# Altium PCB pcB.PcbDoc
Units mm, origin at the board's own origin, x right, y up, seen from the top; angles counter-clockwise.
Board outline 112 x 24 mm, 2 copper layers (TopLayer, BottomLayer); 32 components, 27 nets, 88 pads, 0 vias.
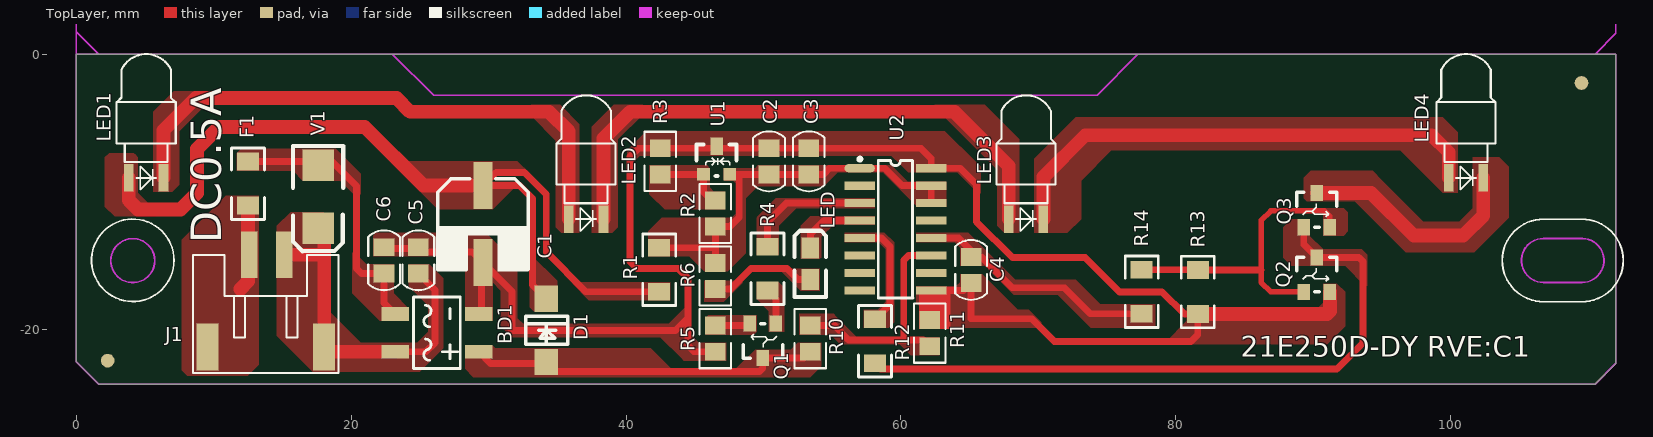
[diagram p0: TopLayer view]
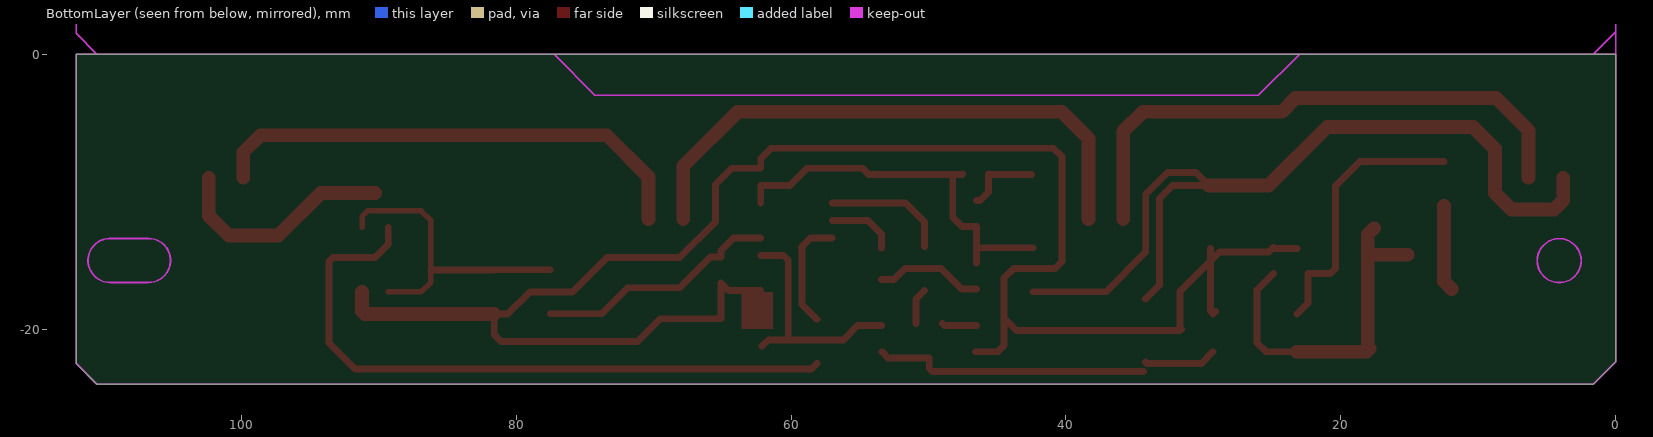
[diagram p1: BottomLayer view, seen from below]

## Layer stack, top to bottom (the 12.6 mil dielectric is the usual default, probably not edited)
TopLayer: signal copper 0.0356
Dielectric: core 0.32, FR-4, Dk 4.8
BottomLayer: signal copper 0.0356

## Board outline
112.003,-22.5 110.5,-24.003 1.641,-24.003 0,-22.362 0,0 112,0

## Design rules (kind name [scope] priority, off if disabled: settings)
Clearance Clearance_1 [InNet(GND)] p1: gap=0.5
Clearance [All] p2 off: gap=0.3
PlaneConnect [All] p1: planeconnectstyle=Direct reliefexpansion=0.508 reliefentries=4 reliefconductorwidth=0.254 reliefairgap=0.254
PolygonConnect [All] p1: connectstyle=Direct reliefconductorwidth=0.254 reliefentries=4 polygonreliefangle="90 Angle"
RoutingVias [All] p1: holewidth=0.5 width=0.8 viastyle="Through Hole" minholewidth=0.3 minwidth=0.6 maxholewidth=1 maxwidth=1.5
SilkscreenOverComponentPads [All] p1: minsilkscreentomaskgap=0.254
SolderMaskExpansion [All] p1: expansion=0.102
TestPointUsage [All] p1: valid=0 allowmultiple=FALSE
Testpoint [All] p1: side=3 testpointundercomponent=TRUE minsize=1.016 maxsize=2.54 preferedsize=1.524 minholesize=0.508 maxholesize=1.016 preferedholesize=0.813 testpointgrid=0.025 style=297 order=0-112345678
Width [All] p1: maxlimit=5 minlimit=0.254 preferedwidth=0.254 toplayer_prefwidth=0.5 bottomlayer_prefwidth=0.5 minimp=50.000000 maximp=50.000000 favimp=50.000000
22 further rules are at their usual default settings.

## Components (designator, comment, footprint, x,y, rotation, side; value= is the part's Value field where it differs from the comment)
BD1 "MB10S" BM6S 23.2,-18.9 r0 top
C1 "22uf/50V" CES6.3 26,-7.7 r0 top
C2 "0805 105/50V 0.1uf  X7R" 0805-C 50.4,-7.8 r270 top
C3 "0805 104/50V 0.1uf  X7R" 0805-C 53.3,-7.8 r270 top
C4 "0805 104/50V 0.1uf  X7R" 0805-C 65.1,-15.7 r90 top
C5 "0805 30PF/50V  X7R" 0805-C 24.9,-15 r270 top
C6 "0805 30PF/50V  X7R" 0805-c 22.4,-15 r90 top
D1 "ES1J" sma 34.2,-20.1 r180 top
F1 "(贴片0.5A)" 1206 12.521,-9.414 r90 top
J1 "卧插座子2.54mm 2P" XH-2.5-2PTW 12.6,-14.6 r0 top
LED "" LED0805 53.4,-16.4 r90 top
LED1 "" LED2_l 5.1,-9 r0 top locked
LED2 "" LED2_l 37.1,-12 r0 top locked
LED3 "" LED2_l 69.1,-12 r0 top locked
LED4 "" LED2_l 101.1,-9 r0 top locked
Q1 "BC846ALT1" SOT-23 50.9,-19.6 r180 top
Q2 "s8050" SOT-23 89.3,-17.3 r0 top
Q3 "s8050" SOT-23 89.3,-12.6 r0 top
R1 "1206 4.7K±5%" 1206 42.4,-15.7 r270 top
R2 "0805 10K±5%" 0805 46.5,-11.6 r270 top
R3 "0805 10K±5%" 0805 42.5,-7.8 r270 top
R4 "1206 1KΩ±5%" 1206 50.3,-15.6 r90 top
R5 "0805 100Ω±5%" 0805 46.5,-20.7 r90 top
R6 "0805 20K±5%" 0805 46.5,-16.15 r90 top
R10 "0805 200K±5%" 0805 53.4,-20.7 r270 top
R11 "0805 30K±5%" 0805 62.1,-20.3 r270 top
R12 "1206 4.7K±5%" 1206 58.1,-20.9 r270 top
R13 "1206 51Ω±5%" 1206 81.6,-17.3 r90 top
R14 "1206 10K±5%" 1206 77.5,-17.3 r270 top
U1 "TL431" SOT23-A2 46.6,-6.7 r0 top
U2 "SOP16" SOP-16b 57,-8.3 r0 top
V1 "P6KE36CA" SMT_TVS 17.6,-8.1 r270 top

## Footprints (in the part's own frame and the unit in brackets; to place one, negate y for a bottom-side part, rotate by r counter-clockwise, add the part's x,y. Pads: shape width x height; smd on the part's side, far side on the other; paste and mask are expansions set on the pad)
0805 [mm]
  rect 1.3x1.5 smd: 1(-0.95,0) 2(0.95,0)
  silkscreen extent -2.15,-1.15 2.15,1.15
0805-C [mm]
  rect 1.3x1.5 smd: 1(-0.95,0) 2(0.95,0)
  silkscreen extent -2.18,-1.15 2.18,1.15
0805-c [mm]
  rect 1.3x1.5 smd: 1(-0.95,0) 2(0.95,0)
  silkscreen extent -2.18,-1.15 2.18,1.15
1206 [mm]
  rect 1.3x1.6 smd: 1(-1.61,0.009) 2(1.59,0.009)
  silkscreen extent -2.61,-1.19 2.59,1.21
BM6S [mm]
  rect 2x1 smd: 1(0,0) 2(0,-2.75) 3(6.096,-2.75) 4(6.096,0)
  silkscreen extent 1.35,-3.97 4.75,1.23
CES6.3 [mm]
  rect 1.4x3.4 smd: 1(3.596,-1.864) 2(3.596,-7.464)
  silkscreen extent 0.3,-8.1 6.9,-1.36
LED2_l [mm]
  rect 0.7x2 smd: A(-1.26,0) K(1.26,0)
  silkscreen extent -2.15,-0.87 2.15,9
LED0805 [mil]
  rect 60x50 smd: A(0,-0.31) K(90,-0.31)
  silkscreen extent -50,-45 140,45
sma [mm]
  rect 1.7x1.905 smd: A(-0.003,2.302) K(-0.003,-2.298)
  silkscreen extent -1.58,-1.01 1.5,1.02
SMT_TVS [mil]
  rect 90x90 smd: A(0,0) K(180,0)
  silkscreen extent -56,-72 246,72
SOP-16b [mm]
  oval 2.2x0.6 smd: 1(0,0)
  rect 2.2x0.6 smd: 2(0,-1.27) 3(0,-2.54) 4(0,-3.81) 5(0,-5.08) 6(0,-6.35) 7(0,-7.62) 8(0,-8.89) 9(5.2,-8.89) 10(5.2,-7.62) 11(5.2,-6.35) 12(5.2,-5.08) 13(5.2,-3.81) 14(5.2,-2.54) 15(5.2,-1.27) 16(5.2,0)
  silkscreen extent -0.11,-9.44 3.87,0.79
SOT23-A2 [mil]
  rect 36x36 smd: 1(-38,-80) 2(37,-80)
  rect 36x50 smd: 3(0,0)
  silkscreen extent -58,-85 57,5
SOT-23 [mm]
  rect 0.918x1.18 smd: 1(0,0) 2(1.9,0) 3(0.95,2.5)
  silkscreen extent -0.51,0 2.39,2.54
XH-2.5-2PTW [mm]
  rect 1.6x3.4 smd: 0(-3.05,-6.7) 0(5.45,-6.7)
  rect 1.2x3.4 smd: 1(0,0) 2(2.54,0)
  silkscreen extent -4.1,-8.6 6.5,0

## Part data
BD1: library part BRIDGE2
C1 C2 C3 C4 C5 C6: library part CAP
D1: library part Diode, "Common Diode"
F1: library part FUSE1
J1: library part CON2
LED LED1 LED2 LED3 LED4: library part LED
Q1 Q2 Q3: library part NPN
R1 R2 R3 R5 R12 R14: library part RES1
R4 R10 R11 R13: library part RES2
R6: library part RES
U1: library part HT66F004_SOP16
U2: library part HT7463B
V1: library part TVS1

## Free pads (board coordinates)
  round 1 smd: 0(2.3,-22.3) 0(109.5,-2.1)

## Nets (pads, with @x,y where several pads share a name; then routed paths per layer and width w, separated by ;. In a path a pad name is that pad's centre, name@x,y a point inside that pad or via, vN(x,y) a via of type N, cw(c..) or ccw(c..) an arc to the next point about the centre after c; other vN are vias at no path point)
5.0V: C2.2 C3.2 R1.1 R2.2 R6.2 U1.2 U2.1 U2.14 U2.15 | length 28.6
  TopLayer w0.5: R1.1 46.41,-14.09 46.5,-14 ; R6.2 46.5,-14 ; U1.2 47.558,-8.75 48.24,-8.75 ; C3.2@53.988,-8.732 C3.2@54,-8.72 ; U2.14 U2.15 60.07,-9.57 58.8,-8.3 U2.1 54.8,-8.3 54.35,-8.75 C3.2 C2.2 48.24,-8.75 ; 46.5,-14 R2.2 47.55,-12.55 48.24,-11.86 48.24,-8.75
ADBT: U2.10
ALD1: C4.2 R14.2 U2.12 | length 17.9
  TopLayer w0.5: U2.12 64.2,-13.38 65.1,-14.28 C4.2 65.85,-14.75 68.1,-17 71.9,-17 73.79,-18.89 R14.2
CHARGE: U2.2
EN1: R12.1 U2.5 | length 8.2
  TopLayer w0.5: U2.5 58.58,-13.38 59.2,-14 59.2,-18.2 R12.1
EN2: U2.6
EN3: U2.13
GND: BD1.4 C1.2 C2.1 C3.1 C4.1 C5.1 C6.2 Q2.2 R3.1 R5.1 R11.1 R13.1 U1.3 U2.9 U2.16 | length 135.3
  TopLayer w0.5: 23.2,-14.15 C5.1@24.9,-14.15 ; C5.1 25.25,-14.4 28.832,-14.4 C1.2@29.496,-15.064 ; BD1.4@29.111,-18.715 BD1.4 29.496,-18.7 C1.2@29.496,-15.064 ; C1.2@29.496,-14.15 C1.2@29.496,-15.064 ; 31.6,-20 31.7,-20.1 ; 31.9,-20.1 32.4,-20.1 ; R5.1@46.6,-21.65 R5.1 44.95,-21.65 44.5,-21.2 44.5,-19.2 ; U2.9 64.56,-17.19 C4.1 65.1,-19.25 69.5,-19.25 71.15,-20.9 81.1,-20.9 81.591,-20.409 R13.1 80.61,-18.91 79,-17.3 75.9,-17.3 73.4,-14.8 68.1,-14.8 65.5,-12.2 65.5,-9.5 64.3,-8.3 U2.16 62.2,-7.6 61.45,-6.85 R3.1 40.9,-6.85 40.3,-7.45 40.3,-15.1 40.8,-15.6 43.8,-15.6 44.5,-16.3 44.5,-19.2 ; C1.2@29.496,-15.064 C1.2 31.7,-17.268 31.7,-20.1 ; 31.7,-20.1 32.4,-20.1 ; 32.4,-20.1 43.6,-20.1 44.5,-19.2
  TopLayer w1: R13.1 90.99,-18.91 91.2,-18.7 Q2.2
LED: LED.K U2.4 | length 5
  TopLayer w0.5: LED.K 53.408,-13.092 54.39,-12.11 U2.4
NetBD1_1: BD1.1 C6.1 F1.2 V1.A | length 20.1
  TopLayer w0.5: F1.2 18.624,-7.824 20.4,-9.6 20.4,-15.6 20.75,-15.95 C6.1 22.4,-18.1 BD1.1
NetBD1_2: BD1.2 C5.2 J1.0@18.05,-21.3 J1.2 V1.K | length 25.8
  TopLayer w0.5: BD1.2 25.45,-21.65 26.1,-21 26.1,-17.15 C5.2
  TopLayer w1: J1.2 18.05,-14.6 ; V1.K 18.05,-13.122 18.05,-14.6 ; J1.0@17.925,-21.425 18.15,-21.65 BD1.2 ; J1.0@18.05,-21.3 18.05,-14.6
NetF1_1: F1.1 J1.1 | length 6.3
  TopLayer w1: 11.951,-17.084 12.512,-16.523 F1.1
NetLED1_K: LED1.K LED2.A | length 41.3
  TopLayer w1: LED1.K 6.36,-5.54 8.7,-3.2 23.3,-3.2 24.3,-4.2 34.4,-4.2 35.84,-5.64 LED2.A
NetLED2_K: LED2.K LED3.A | length 41.6
  TopLayer w1: LED2.K 38.36,-6.14 40.3,-4.2 63.9,-4.2 67.84,-8.14 LED3.A
NetLED3_K: LED3.K LED4.A | length 36.2
  TopLayer w1: LED3.K 70.36,-8.94 73.4,-5.9 98.6,-5.9 99.84,-7.14 LED4.A
NetLED4_K: LED4.K Q3.3 | length 16.7
  TopLayer w1: Q3.3 94.2,-10.1 97.3,-13.2 100.9,-13.2 102.36,-11.74 LED4.K
NetLED_A: LED.A R6.1 | length 7.9
  TopLayer w0.5: R6.1 47.6,-17.1 49.1,-15.6 51.7,-15.6 52.5,-16.4 LED.A
NetQ1_1: Q1.1 R4.1 | length 2.6
  TopLayer w0.5: R4.1 50.9,-17.819 Q1.1
NetQ1_2: Q1.2 R5.2 | length 2.6
  TopLayer w0.5: R5.2 48.85,-19.75 Q1.2
NetQ2_1: Q2.1 Q3.2 R13.2 R14.1 | length 23.2
  TopLayer w0.4: Q2.1 86.9,-17.3 86.2,-16.6 86.2,-15.7 86.2,-12.1 86.9,-11.4 90.8,-11.4 91.2,-11.8 Q3.2 Q3.2@91.2,-12.2
  TopLayer w0.5: R14.1 R13.2@81.571,-15.69 ; R13.2 86.19,-15.71 86.2,-15.7
NetQ2_3: Q2.3 Q3.1 R12.2 | length 48.4
  TopLayer w0.5: R12.2 58.519,-22.9 91.7,-22.9 93.6,-21 93.6,-15.1 93.3,-14.8 Q2.3 89.3,-13.85 Q3.1
NetR2_1: R2.1 R3.2 U1.1 | length 5.6
  TopLayer w0.5: R3.2 U1.1@45.635,-8.75 ; R2.1 46.25,-10.65 45.635,-10.035 U1.1@45.635,-8.75 ; U1.1@45.635,-8.75 45.653,-8.75 U1.1 U1.1@45.635,-8.75
PI: R10.1 R11.2 U2.11 | length 17.2
  TopLayer w0.5: R10.1 55.15,-19.75 56.2,-20.8 60.1,-20.8 ; R11.2 61.65,-20.8 60.2,-20.8 60.2,-15 60.55,-14.65 U2.11
PO: R4.2 U2.3 | length 9.1
  TopLayer w0.5: R4.2 50.291,-12.209 51.66,-10.84 U2.3
SENSOR: U2.8
V+: BD1.3 D1.A Q1.3 R10.2 | length 25.4
  TopLayer w0.5: BD1.3 30.146,-22.5 34.105,-22.5 D1.A ; D1.A@34.368,-23.1 49.7,-23.1 49.95,-22.85 Q1.3 52.95,-22.1 R10.2
VV+: C1.1 D1.K LED1.A R1.2 | length 64.8
  TopLayer w0.5: D1.K 33.2,-16.798 33.2,-10.5 32.264,-9.564 C1.1 30.56,-8.6 32.6,-8.6 34.2,-10.2 34.2,-14.4 37.09,-17.29 R1.2
  TopLayer w1: LED1.A 3.84,-10.64 4.5,-11.3 7.6,-11.3 8.8,-10.1 8.8,-6.9 10.4,-5.3 21,-5.3 25.264,-9.564 C1.1
pads on no net: J1.0@9.55,-21.3 U2.7

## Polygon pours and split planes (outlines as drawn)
5.0V on TopLayer "Bottom Layer-No Net" (solid, remove dead copper, pour order 1000): 41.6,-14.7 44.6,-14.7 45.7,-15.8 47.4,-15.8 48.5,-14.7 48.7,-14.5 48.7,-8.8 48,-8.8 48,-11.6 47.7,-11.9 42.6,-11.9 41.6,-12.9
5.0V on TopLayer "Bottom Layer-No Net" (solid, remove dead copper, pour order 1001): 47.1,-8.3 49.4,-8.3 49.6,-8.1 59.3,-8.1 60.1,-8.9 60.5,-9.3 63.3,-9.3 63.3,-11.1 61.2,-11.1 58.8,-8.7 58.7,-8.6 56.5,-8.6 55.4,-8.6 54.4,-9.6 49.6,-9.6 48.6,-10.6 48.1,-10.6 48.1,-9.5 47.8,-9.2 47.1,-9.2
ALD1 on TopLayer "Bottom Layer-No Net" (solid, remove dead copper, pour order 1002): 61.1,-13.7 63.9,-13.7 64.3,-14.1 64.3,-15.4 66.1,-15.4 67.5,-16.8 68.2,-17.5 71.4,-17.5 73.8,-19.9 78.5,-19.9 78.5,-18.2 74.5,-18.2 73,-16.7 72.7,-16.4 69.5,-16.4 68.3,-16.4 65.3,-13.4 64.9,-13 61.1,-13
EN1 on TopLayer "Bottom Layer-No Net" (solid, remove dead copper, pour order 1003): 57.3,-19.9 59.1,-19.9 59.4,-19.6 59.5,-19.5 59.5,-15.7 59.5,-13.7 58.8,-13 55.9,-13 55.9,-13.7 58.4,-13.7 58.9,-14.2 58.9,-18 58.3,-18.6 57.3,-18.6
GND on TopLayer "Bottom Layer-No Net" (solid, remove dead copper, pour order 1004): 61.1,-16.9 64,-16.9 64.3,-16.6 64.3,-16 65.9,-16 68.5,-18.6 69.1,-18.6 69.3,-18.6 70.2,-19.5 70.2,-19.8 70.1,-19.9 63.1,-19.9 62.9,-19.9 61.1,-18.1
GND on TopLayer "Bottom Layer-No Net" (solid, remove dead copper, pour order 1005): 90.7,-16.7 90.7,-18.1 90.4,-18.4 80.8,-18.4 80.8,-19.4 79.1,-21.1 91,-21.1 92.2,-19.9 92.3,-19.8 92.3,-17.3 91.7,-16.7
GND on TopLayer "Bottom Layer-No Net" (solid, remove dead copper, pour order 1006): 61.1,-8.6 64.1,-8.6 65.4,-9.9 65.8,-10.3 65.8,-8.2 65.4,-7.8 63.2,-5.6 41.3,-5.6 41.3,-5.8 40.1,-7 40.1,-7.8 40.6,-7.8 40.9,-7.5 41,-7.4 46.8,-7.4 59.3,-7.4 60.5,-8.6
GND on TopLayer "Bottom Layer-No Net" (solid, remove dead copper, pour order 1007): 47.3,-21 45.3,-21 44.7,-20.4 44.7,-18 43.1,-19.6 32.1,-19.6 30.9,-19.6 31.9,-20.6 32.9,-20.6 42.5,-20.6 44,-22.1 44.2,-22.3 47.3,-22.3
LED on TopLayer "Bottom Layer-No Net" (solid, remove dead copper, pour order 1010): 52.7,-14.9 52.7,-12.5 53.4,-11.8 58.1,-11.8 58.1,-12.4 55.1,-12.4 54.2,-13.3 54.2,-14.8 54.1,-14.9
NetF1_1 on TopLayer "Bottom Layer-No Net" (solid, remove dead copper, pour order 1013): 13.3,-10.3 13.3,-22.6 12.5,-23.4 8.1,-23.4 7.7,-23 7.7,-13.5 10.9,-10.3
NetLED1_K on TopLayer "Bottom Layer-No Net" (solid, remove dead copper, pour order 1014): 5.6,-10 5.6,-4.2 7.1,-2.7 9.8,-2.7 9.8,-3.3 9.1,-4 7.5,-5.6 7.5,-9.5 7,-10
NetLED2_K on TopLayer "Bottom Layer-No Net" (solid, remove dead copper, pour order 1015): 37.5,-13 37.5,-5.3 39.1,-3.7 41.2,-3.7 41.2,-4.4 39.4,-6.2 39.4,-12.6 39,-13
NetLED1_K on TopLayer "Bottom Layer-No Net" (solid, remove dead copper, pour order 1016): 36.6,-13 36.6,-5.1 35.2,-3.7 33.1,-3.7 33.1,-4.5 34.9,-6.3 34.9,-7 34.9,-12.6 35.3,-13
NetLED2_K on TopLayer "Bottom Layer-No Net" (solid, remove dead copper, pour order 1017): 68.6,-13 68.6,-6.2 66.9,-4.5 66.1,-3.7 62.3,-3.7 67,-8.4 67,-9.2 67,-12.5 67.5,-13
NetLED3_K on TopLayer "Bottom Layer-No Net" (solid, remove dead copper, pour order 1018): 69.7,-13 69.7,-7.6 72.5,-4.8 72.7,-4.6 81.4,-4.6 99.4,-4.6 100.5,-5.7 100.5,-10.1 99.4,-10.1 97.8,-8.5 96.3,-7 95.4,-7 75.3,-7 73.1,-9.2 73.1,-12 72.1,-13
NetLED4_K on TopLayer "Bottom Layer-No Net" (solid, remove dead copper, pour order 1019): 101.6,-7.5 101.6,-11.2 100.7,-12.1 100.6,-12.2 98.3,-12.2 98,-12.2 95,-9.2 94.3,-8.5 89.8,-8.5 89.3,-9 89.3,-9.1 89.3,-10.5 89.5,-10.7 93,-10.7 95.4,-13.1 96.7,-14.4 101.5,-14.4 101.7,-14.4 104.2,-11.9 104.2,-8.2 103.5,-7.5
NetLED_A on TopLayer "Bottom Layer-No Net" (solid, remove dead copper, pour order 1020): 54.1,-15.6 51.4,-15.6 51.3,-15.6 51.3,-15.8 52.7,-17.2 54.1,-17.2
NetLED_A on TopLayer "Bottom Layer-No Net" (solid, remove dead copper, pour order 1021): 45.7,-16.5 48.6,-16.5 47.1,-18 45.7,-18
NetQ1_1 on TopLayer "Bottom Layer-No Net" (solid, remove dead copper, pour order 1022): 50.4,-20.2 50.4,-18.7 49.5,-17.8 49.5,-16.6 51.1,-16.6 51.5,-17 51.5,-20.2
NetQ1_2 on TopLayer "Bottom Layer-No Net" (solid, remove dead copper, pour order 1023): 45.8,-20.4 49.3,-20.4 49.5,-20.2 49.5,-19 46,-19 45.8,-19.2
NetQ2_1 on TopLayer "Bottom Layer-No Net" (solid, remove dead copper, pour order 1024): 90.7,-13.2 90.7,-11.7 90.2,-11.2 92.2,-11.2 92.5,-11.5 92.5,-12.9 92.2,-13.2
NetQ2_3 on TopLayer "Bottom Layer-No Net" (solid, remove dead copper, pour order 1025): 89.7,-12 89.7,-13.2 90.7,-14.2 93.5,-14.2 93.9,-14.6 93.9,-17 92.3,-15.4 91,-15.4 88.4,-15.4 87.8,-14.8 87.8,-12.6 88.4,-12
NetR2_1 on TopLayer "Bottom Layer-No Net" (solid, remove dead copper, pour order 1026): 47.2,-11.3 42.8,-11.3 41.8,-10.3 41.7,-10.2 41.7,-8.1 45.9,-8.1 46.1,-8.3 46.1,-9.7 46.4,-10 47.2,-10
PI on TopLayer "Bottom Layer-No Net" (solid, remove dead copper, pour order 1027): 62.8,-20.6 56.8,-20.6 55.3,-19.1 55.1,-18.9 52.6,-18.9 52.6,-20.4 54.9,-20.4 55.6,-21.1 59.9,-21.1 60.7,-21.9 62.8,-21.9
PO on TopLayer "Bottom Layer-No Net" (solid, remove dead copper, pour order 1028): 58.1,-10.5 50.9,-10.5 49.6,-11.8 49.5,-11.9 49.5,-14.6 51.1,-14.6 51.1,-12.5 52.4,-11.2 58.1,-11.2
V+ on TopLayer "Bottom Layer-No Net" (solid, remove dead copper, pour order 1029): 54.2,-21 52.5,-21 52,-21.5 49.4,-21.5 48,-22.9 43.3,-22.9 41.9,-21.5 41.8,-21.4 30.5,-21.4 30.3,-21.2 28.3,-21.2 28.3,-22.9 28.9,-23.5 53.4,-23.5 54.2,-22.7
VV+ on TopLayer "Bottom Layer-No Net" (solid, remove dead copper, pour order 1032): 5.8,-11.8 2.8,-11.8 2.1,-11.1 2.1,-7.5 2.4,-7.2 4.2,-7.2 4.3,-7.3 4.5,-7.5 4.5,-9.4 4.5,-10.1 5.8,-11.4
GND on TopLayer "Bottom Layer-No Net" (solid, remove dead copper, pour order 1000): 32.4,-20.6 31.7,-20.6 30.9,-19.8 30.9,-17.2 30.3,-16.6 30.3,-19.4 28.3,-19.4 28.3,-15.8 27.5,-15 27.2,-14.7 24.1,-14.7 21.6,-14.7 21.6,-13.2 21.8,-13 29.8,-13 30.3,-13.5 32.1,-15.3 32.1,-18.1 32.1,-19.2 32.6,-19.7 32.6,-20.6
VV+ on TopLayer "Bottom Layer-No Net" (solid, remove dead copper, pour order 1001): 43.2,-16.6 36,-16.6 37.3,-17.9 43.2,-17.9
VV+ on TopLayer "Bottom Layer-No Net" (solid, remove dead copper, pour order 1002): 35,-18.7 35,-16.5 33,-14.5 33,-18.4 33.3,-18.7
VV+ on TopLayer "Bottom Layer-No Net" (solid, remove dead copper, pour order 1003): 30.3,-7.8 22.8,-7.8 26.3,-11.3 30.3,-11.3 31.9,-9.7 31.9,-9.3 29.8,-9.3 29.6,-9.5 30.3,-8.8 32.7,-8.8 33.1,-8.8 32.1,-7.8 31.7,-7.8
NetBD1_1 on TopLayer "Bottom Layer-No Net" (solid, remove dead copper, pour order 1004): 24.1,-19.4 24.1,-18.4 23.2,-17.5 23.1,-17.4 23.1,-15.3 21.1,-15.3 20.1,-14.3 20.1,-17.4 22.1,-19.4
NetBD1_2 on TopLayer "Bottom Layer-No Net" (solid, remove dead copper, pour order 1005): 24.2,-15.3 24.2,-16.9 25.6,-18.3 25.6,-20.2 24.8,-21 20.7,-21 18.2,-18.5 18,-18.3 18,-11.5 15.6,-11.5 14.6,-12.5 14.6,-20.5 17.2,-23.1 25,-23.1 26.7,-21.4 26.7,-16.3 25.7,-15.3
NetBD1_1 on TopLayer "Bottom Layer-No Net" (solid, remove dead copper, pour order 1006): 20.7,-10.2 20.7,-8.7 18.9,-6.9 12,-6.9 11.7,-7.2 11.7,-8.5 15.8,-8.5 16.5,-9.2 19.2,-9.2 20.2,-10.2

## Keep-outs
KeepOutLayer:
  circle w0.127: c4.125,80.978 r1.6
  circle w0.127: c4.125,56.978 r1.6
  circle w0.127: c4.125,32.978 r1.6
  circle w0.127: c4.125,8.978 r1.6
  circle w0.127: c4.125,-15.022 r1.6
  lines w0.1: 0,1.7 0,0 ; 0,25.7 0,24 ; 0,49.7 0,48 ; 0,73.7 0,72 ; 77.235,-0.024 74.26,-3 26,-3 23,0 0,0 ; 77.235,23.976 74.26,21 26,21 23,24 0,24 ; 77.235,47.976 74.26,45 26,45 23,48 0,48 ; 77.235,71.976 74.26,69 26,69 23,72 0,72 ; 77.235,95.976 74.26,93 26,93 23,96 0,96 0,73.638 1.638,72 1.7,72 ; 77.26,0 112,0 112,-22.5 110.5,-24 1.7,-24 1.638,-24 0,-22.362 0,0 ; 77.26,24 112,24 112,1.5 110.5,0 1.7,0 ; 77.26,48 112,48 112,25.5 110.5,24 1.7,24 ; 77.26,72 112,72 112,49.5 110.5,48 1.7,48 ; 77.26,96 112,96 112,73.5 110.5,72 1.7,72 ; 0,0 1.7,0 ; 0,24 1.7,24 ; 0,24 0,1.638 1.638,0 1.7,0 ; 0,48 1.7,48 ; 0,48 0,25.638 1.638,24 1.7,24 ; 0,72 1.7,72 ; 0,72 0,49.638 1.638,48 1.7,48
  lines w0.127: 109.534,-13.41 106.734,-13.41 ccw(c106.734,-15.01) 106.734,-16.61 109.534,-16.61 ccw(c109.534,-15.01) 109.587,-13.411 ; 109.534,10.59 106.734,10.59 ccw(c106.734,8.99) 106.734,7.39 109.534,7.39 ccw(c109.534,8.99) 109.587,10.589 ; 109.534,34.59 106.734,34.59 ccw(c106.734,32.99) 106.734,31.39 109.534,31.39 ccw(c109.534,32.99) 109.587,34.589 ; 109.534,58.59 106.734,58.59 ccw(c106.734,56.99) 106.734,55.39 109.534,55.39 ccw(c109.534,56.99) 109.587,58.589 ; 109.534,82.59 106.734,82.59 ccw(c106.734,80.99) 106.734,79.39 109.534,79.39 ccw(c109.534,80.99) 109.587,82.589
  lines w0.254: -6.508,-22.476 -6,-24 ; -6.508,94.476 -6,96 ; -6.254,-24 -5.746,-24 ; -6.254,96 -5.746,96 ; -6,30.261 -6,-24 ; -6,41.739 -6,96 ; -5.492,-22.476 -6,-24 ; -5.492,94.476 -6,96 ; -3.508,-22.476 -3,-24 ; -3.508,-1.524 -3,0 ; -3.254,-24 -2.746,-24 ; -3.254,0 -2.746,0 ; -3,-17.104 -3,-24 ; -3,-6.896 -3,0 ; -2.492,-22.476 -3,-24 ; -2.492,-1.524 -3,0 ; 0,-27.254 0,-26.746 ; 1.524,-27.508 0,-27 ; 1.524,-26.492 0,-27 ; 50.388,-27 0,-27 ; 61.612,-27 112,-27 ; 110.476,-27.508 112,-27 ; 110.476,-26.492 112,-27 ; 112,-27.254 112,-26.746
  text "120 (mm)" at -5.086,30.515 h1.52 r90
  text "24 (mm)" at -2.086,-16.85 h1.52 r90
  text "112 (mm)" at 50.642,-27.914 h1.52

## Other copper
TopLayer:
  rectangle net GND: 61.3,-20 63.6,-17.3

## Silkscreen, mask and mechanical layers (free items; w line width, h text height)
TopOverlay:
  circle w0.127: c4.125,-15 r3
  lines w0.127: 106.734,-18.01 cw(c106.734,-15.01) 106.734,-12.01 109.534,-12.01 cw(c109.534,-15.01) 109.534,-18.01 106.734,-18.01
  text "DC0.5A" at 10.545,-13.762 h2.2 r90
  text "21E250D-DY RVE:C1" at 84.7,-22 h1.5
